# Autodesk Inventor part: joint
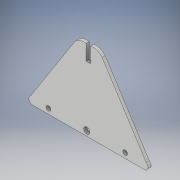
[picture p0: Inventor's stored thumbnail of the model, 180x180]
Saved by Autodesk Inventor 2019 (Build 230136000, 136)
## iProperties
Created: 2020-02
Part Number: joint
Material: Generic
Document SubType Name: Modeling
Designer: shivu
Density: 1 g/cm^3
Appearance: Default
Author: shivu
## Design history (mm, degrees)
sketch "Sketch1"
  geometry: L1 (1, 40)-(1, 50); L2 (0, -2.252)-(34.857, -2.252); L3 (34.857, -2.252)-(36.431, -2.252); L4 (8.428, 47.241)-(37.174, 2.288); L5 (-9.428, 47.241)-(-38.174, 2.288); L6 (-2, 40)-(-2, 50); L7 (0, -2.252)-(-34.857, -2.252); L8 (-34.857, -2.252)-(-36.431, -2.252); L9 (-2, 40)-(1, 40); C1 r 2 at (-1.5, 1.058); C2 r 1.5 at (23.5, 1.058); C3 r 1.5 at (-26.5, 1.058); A1 r 7.887 centre (2.34, 42.227) between (8.428, 47.241) and (1, 50); A2 r 2.486 centre (35.872, 0.17) between (36.431, -2.252) and (37.174, 2.288); A3 r 7.887 centre (-3.34, 42.227) between (-2, 50) and (-9.428, 47.241); A4 r 2.486 centre (-36.819, 0.203) between (-38.174, 2.288) and (-36.431, -2.252); 1 further point
  constraints: 18 end point, 8 point on circle, 7 centre point, 3 horizontal
  dimensions: "d5" = 10 distance of L1.start L1.end; "d12" = 10 distance of L6.start L6.end; "d34" = 3 distance of L6.start L1.start
extrude "Extrusion6" new body sketch "Sketch1" distance "d32" = 2; taper "d33" = 0 deg
body "Solid2"
